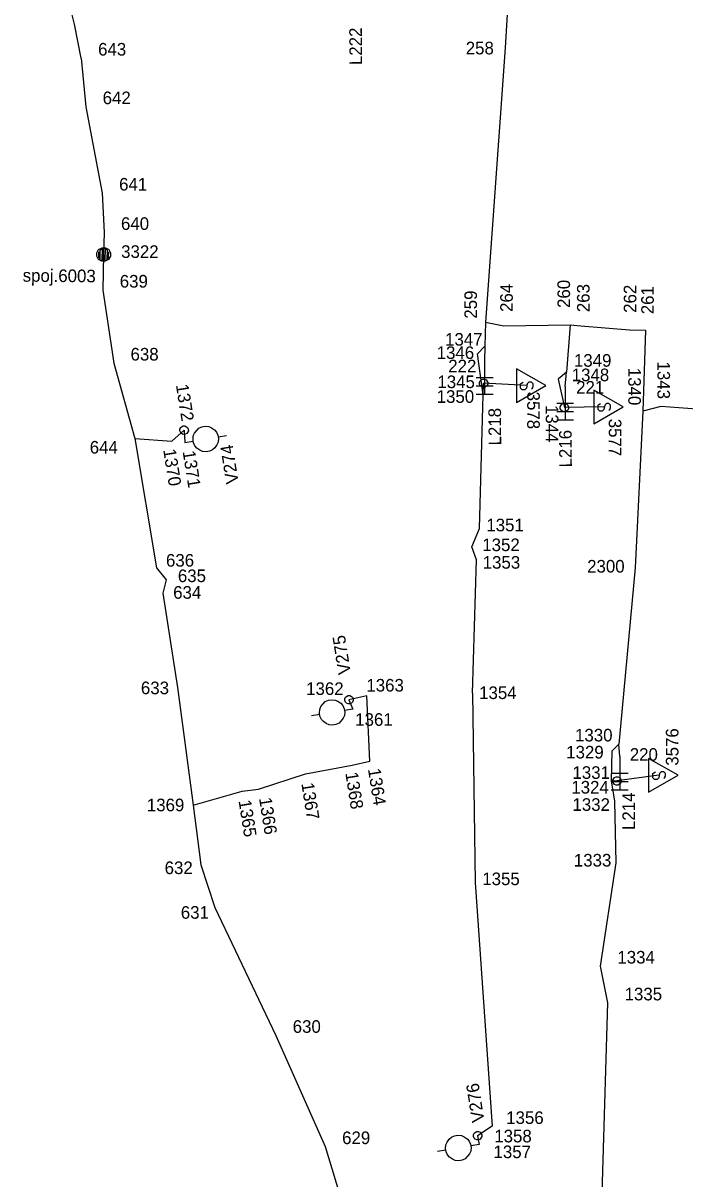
# Model space of a CAD drawing. Extents: x -535557 to -534097, y -1142175 to -1136716.
# Drawn here: x -534529.8 to -534490.4, y -1140672.6 to -1140603.8 of the extents above; entities that cross this region are included whole.
import ezdxf

# ---------------------------------------------------------------- set-up
doc = ezdxf.new("R2010")
doc.units = 0
doc.layers.add('Default', color=7, linetype='Continuous')
doc.layers.add('SS_SZDC', color=7, linetype='Continuous')

# ---------------------------------------------------------------- blocks, each defined once
blk = doc.blocks.new('POINT_DISPLAY')
at = {"layer": 'Default'}
blk.add_line((0, 0), (0, 0), dxfattribs=at)

msp = doc.modelspace()

# ---------------------------------------------------------------- linework, layer by layer
at = {"layer": 'SS_SZDC'}
for p, q in [((-534500.069, -1140588.51), (-534501.09, -1140605.28)), ((-534526.72, -1140603.879), (-534528.6, -1140596)), ((-534526.31, -1140605.889), (-534526.72, -1140603.879)), ((-534501.09, -1140605.28), (-534502.26, -1140621.6)), ((-534526.31, -1140605.889), (-534526.039, -1140608.78)), ((-534526.039, -1140608.78), (-534525.06, -1140613.92)), ((-534525.06, -1140613.92), (-534524.949, -1140616.26)), ((-534524.949, -1140616.26), (-534524.979, -1140617.569)), ((-534525.38, -1140617.666), (-534525.379, -1140617.466)), ((-534525.379, -1140617.466), (-534525.277, -1140617.267)), ((-534525.278, -1140617.417), (-534525.281, -1140617.717)), ((-534525.277, -1140617.267), (-534525.076, -1140617.169)), ((-534525.182, -1140617.868), (-534525.177, -1140617.318)), ((-534525.177, -1140617.318), (-534525.076, -1140617.219)), ((-534525.076, -1140617.219), (-534525.083, -1140617.919)), ((-534525.076, -1140617.169), (-534524.876, -1140617.17)), ((-534524.983, -1140617.919), (-534524.976, -1140617.22)), ((-534524.883, -1140617.92), (-534524.876, -1140617.22)), ((-534524.876, -1140617.17), (-534524.677, -1140617.272)), ((-534524.876, -1140617.22), (-534524.777, -1140617.321)), ((-534524.777, -1140617.321), (-534524.782, -1140617.871)), ((-534524.681, -1140617.722), (-534524.678, -1140617.422)), ((-534524.677, -1140617.272), (-534524.579, -1140617.473)), ((-534524.579, -1140617.473), (-534524.58, -1140617.673)), ((-534525.282, -1140617.867), (-534525.38, -1140617.666)), ((-534525.083, -1140617.969), (-534525.282, -1140617.867)), ((-534525.281, -1140617.717), (-534525.182, -1140617.868)), ((-534525.083, -1140617.919), (-534524.883, -1140617.92)), ((-534524.883, -1140617.97), (-534525.083, -1140617.969)), ((-534524.979, -1140617.569), (-534525.02, -1140619.69)), ((-534524.682, -1140617.872), (-534524.883, -1140617.97)), ((-534524.782, -1140617.871), (-534524.681, -1140617.722)), ((-534524.58, -1140617.673), (-534524.682, -1140617.872)), ((-534525.02, -1140619.69), (-534524.38, -1140624.03)), ((-534502.26, -1140621.6), (-534502.289, -1140623.03)), ((-534502.26, -1140621.6), (-534501.159, -1140621.819)), ((-534501.159, -1140621.819), (-534497.21, -1140621.75)), ((-534497.21, -1140621.75), (-534497.43, -1140624.569)), ((-534497.21, -1140621.75), (-534496.579, -1140621.819)), ((-534496.579, -1140621.819), (-534493.68, -1140622.049)), ((-534493.68, -1140622.049), (-534492.729, -1140622.069)), ((-534492.729, -1140622.069), (-534492.89, -1140626.889)), ((-534502.729, -1140623.489), (-534502.289, -1140623.03)), ((-534502.289, -1140623.03), (-534502.31, -1140623.909)), ((-534502.399, -1140625.92), (-534502.729, -1140623.489)), ((-534524.38, -1140624.03), (-534523.119, -1140628.52)), ((-534502.31, -1140623.909), (-534502.31, -1140625.909)), ((-534500.419, -1140624.37), (-534500.419, -1140626.37)), ((-534498.669, -1140625.37), (-534500.419, -1140624.37)), ((-534501.81, -1140624.909), (-534502.81, -1140624.909)), ((-534502.62, -1140625.181), (-534502.57, -1140625.081)), ((-534502.57, -1140625.081), (-534502.521, -1140625.03)), ((-534502.521, -1140625.03), (-534502.421, -1140624.98)), ((-534502.421, -1140624.98), (-534502.321, -1140624.979)), ((-534502.321, -1140624.979), (-534502.221, -1140625.029)), ((-534502.221, -1140625.029), (-534502.17, -1140625.078)), ((-534502.17, -1140625.078), (-534502.12, -1140625.178)), ((-534497.43, -1140624.569), (-534497.93, -1140624.989)), ((-534497.93, -1140624.989), (-534497.56, -1140626.68)), ((-534497.52, -1140625.43), (-534497.43, -1140624.569)), ((-534501.81, -1140625.409), (-534502.81, -1140625.409)), ((-534502.619, -1140625.281), (-534502.62, -1140625.181)), ((-534502.569, -1140625.381), (-534502.619, -1140625.281)), ((-534502.518, -1140625.43), (-534502.569, -1140625.381)), ((-534502.418, -1140625.48), (-534502.518, -1140625.43)), ((-534502.318, -1140625.479), (-534502.418, -1140625.48)), ((-534502.399, -1140625.92), (-534502.369, -1140625.229)), ((-534499.819, -1140625.37), (-534502.369, -1140625.229)), ((-534502.218, -1140625.429), (-534502.318, -1140625.479)), ((-534502.169, -1140625.378), (-534502.218, -1140625.429)), ((-534502.119, -1140625.278), (-534502.169, -1140625.378)), ((-534502.12, -1140625.178), (-534502.119, -1140625.278)), ((-534500.419, -1140626.37), (-534498.669, -1140625.37)), ((-534500.169, -1140625.27), (-534500.119, -1140625.22)), ((-534500.169, -1140625.52), (-534500.169, -1140625.27)), ((-534500.069, -1140625.62), (-534500.169, -1140625.52)), ((-534500.119, -1140625.22), (-534500.019, -1140625.17)), ((-534499.919, -1140625.62), (-534500.069, -1140625.62)), ((-534499.819, -1140625.52), (-534499.919, -1140625.62)), ((-534499.769, -1140625.27), (-534499.819, -1140625.52)), ((-534499.669, -1140625.17), (-534499.769, -1140625.27)), ((-534499.519, -1140625.17), (-534499.669, -1140625.17)), ((-534499.419, -1140625.27), (-534499.519, -1140625.17)), ((-534499.519, -1140625.57), (-534499.469, -1140625.52)), ((-534499.469, -1140625.52), (-534499.419, -1140625.42)), ((-534499.419, -1140625.42), (-534499.419, -1140625.27)), ((-534497.52, -1140625.43), (-534497.52, -1140627.43)), ((-534495.81, -1140625.639), (-534495.81, -1140627.639)), ((-534494.06, -1140626.639), (-534495.81, -1140625.639)), ((-534501.81, -1140625.909), (-534502.81, -1140625.909)), ((-534502.609, -1140633.879), (-534502.399, -1140625.92)), ((-534497.02, -1140626.43), (-534498.02, -1140626.43)), ((-534497.76, -1140626.531), (-534497.711, -1140626.48)), ((-534497.711, -1140626.48), (-534497.611, -1140626.43)), ((-534497.611, -1140626.43), (-534497.511, -1140626.429)), ((-534497.511, -1140626.429), (-534497.411, -1140626.479)), ((-534497.411, -1140626.479), (-534497.36, -1140626.528)), ((-534495.51, -1140626.489), (-534495.41, -1140626.439)), ((-534495.06, -1140626.439), (-534495.16, -1140626.539)), ((-534494.91, -1140626.439), (-534495.06, -1140626.439)), ((-534494.81, -1140626.539), (-534494.91, -1140626.439)), ((-534497.02, -1140626.93), (-534498.02, -1140626.93)), ((-534497.81, -1140626.631), (-534497.76, -1140626.531)), ((-534497.809, -1140626.731), (-534497.81, -1140626.631)), ((-534497.759, -1140626.831), (-534497.809, -1140626.731)), ((-534497.708, -1140626.88), (-534497.759, -1140626.831)), ((-534497.608, -1140626.93), (-534497.708, -1140626.88)), ((-534497.508, -1140626.929), (-534497.608, -1140626.93)), ((-534495.21, -1140626.639), (-534497.56, -1140626.68)), ((-534497.408, -1140626.879), (-534497.508, -1140626.929)), ((-534497.359, -1140626.828), (-534497.408, -1140626.879)), ((-534497.36, -1140626.528), (-534497.31, -1140626.628)), ((-534497.309, -1140626.728), (-534497.359, -1140626.828)), ((-534497.31, -1140626.628), (-534497.309, -1140626.728)), ((-534495.81, -1140627.639), (-534494.06, -1140626.639)), ((-534495.56, -1140626.539), (-534495.51, -1140626.489)), ((-534495.56, -1140626.789), (-534495.56, -1140626.539)), ((-534495.46, -1140626.889), (-534495.56, -1140626.789)), ((-534495.31, -1140626.889), (-534495.46, -1140626.889)), ((-534495.21, -1140626.789), (-534495.31, -1140626.889)), ((-534495.16, -1140626.539), (-534495.21, -1140626.789)), ((-534494.91, -1140626.839), (-534494.86, -1140626.789)), ((-534494.86, -1140626.789), (-534494.81, -1140626.689)), ((-534494.81, -1140626.689), (-534494.81, -1140626.539)), ((-534492.89, -1140626.889), (-534493.359, -1140636.209)), ((-534491.829, -1140626.61), (-534492.89, -1140626.889)), ((-534489.149, -1140626.809), (-534491.829, -1140626.61)), ((-534520.39, -1140627.871), (-534520.341, -1140627.82)), ((-534520.341, -1140627.82), (-534520.241, -1140627.77)), ((-534520.241, -1140627.77), (-534520.141, -1140627.769)), ((-534520.141, -1140627.769), (-534520.041, -1140627.819)), ((-534520.041, -1140627.819), (-534519.99, -1140627.868)), ((-534519.316, -1140627.904), (-534519.127, -1140627.822)), ((-534519.127, -1140627.822), (-534518.93, -1140627.79)), ((-534518.93, -1140627.79), (-534518.724, -1140627.806)), ((-534518.724, -1140627.806), (-534518.56, -1140627.881)), ((-534497.02, -1140627.43), (-534498.02, -1140627.43)), ((-534523.119, -1140628.52), (-534520.92, -1140628.67)), ((-534523.119, -1140628.52), (-534521.84, -1140636.219)), ((-534520.92, -1140628.67), (-534520.189, -1140628.02)), ((-534520.44, -1140627.971), (-534520.39, -1140627.871)), ((-534520.439, -1140628.071), (-534520.44, -1140627.971)), ((-534520.389, -1140628.171), (-534520.439, -1140628.071)), ((-534520.338, -1140628.22), (-534520.389, -1140628.171)), ((-534520.238, -1140628.27), (-534520.338, -1140628.22)), ((-534520.138, -1140628.269), (-534520.238, -1140628.27)), ((-534520.189, -1140628.02), (-534520.14, -1140628.75)), ((-534520.038, -1140628.219), (-534520.138, -1140628.269)), ((-534519.989, -1140628.168), (-534520.038, -1140628.219)), ((-534519.99, -1140627.868), (-534519.94, -1140627.968)), ((-534519.939, -1140628.068), (-534519.989, -1140628.168)), ((-534519.94, -1140627.968), (-534519.939, -1140628.068)), ((-534519.662, -1140628.569), (-534519.646, -1140628.364)), ((-534519.646, -1140628.364), (-534519.571, -1140628.2)), ((-534519.571, -1140628.2), (-534519.316, -1140627.904)), ((-534518.56, -1140627.881), (-534518.388, -1140628.004)), ((-534518.388, -1140628.004), (-534518.264, -1140628.136)), ((-534518.264, -1140628.136), (-534518.183, -1140628.325)), ((-534518.183, -1140628.325), (-534518.15, -1140628.522)), ((-534518.15, -1140628.522), (-534518.167, -1140628.728)), ((-534518.166, -1140628.424), (-534517.673, -1140628.342)), ((-534520.14, -1140628.75), (-534519.646, -1140628.668)), ((-534519.646, -1140628.668), (-534519.662, -1140628.569)), ((-534519.63, -1140628.767), (-534519.646, -1140628.668)), ((-534519.548, -1140628.956), (-534519.63, -1140628.767)), ((-534519.425, -1140629.088), (-534519.548, -1140628.956)), ((-534519.252, -1140629.211), (-534519.425, -1140629.088)), ((-534519.088, -1140629.285), (-534519.252, -1140629.211)), ((-534518.496, -1140629.188), (-534518.685, -1140629.27)), ((-534518.364, -1140629.065), (-534518.496, -1140629.188)), ((-534518.241, -1140628.892), (-534518.364, -1140629.065)), ((-534518.167, -1140628.728), (-534518.241, -1140628.892)), ((-534518.883, -1140629.302), (-534519.088, -1140629.285)), ((-534518.685, -1140629.27), (-534518.883, -1140629.302)), ((-534503.069, -1140634.959), (-534502.609, -1140633.879)), ((-534502.789, -1140635.739), (-534503.069, -1140634.959)), ((-534503.029, -1140643.67), (-534502.789, -1140635.739)), ((-534521.84, -1140636.219), (-534521.25, -1140636.92)), ((-534493.359, -1140636.209), (-534494.319, -1140646.709)), ((-534521.25, -1140636.92), (-534521.46, -1140637.709)), ((-534521.46, -1140637.709), (-534520.59, -1140643.329)), ((-534520.59, -1140643.329), (-534519.649, -1140650.329)), ((-534512.048, -1140644.467), (-534511.925, -1140644.294)), ((-534511.925, -1140644.294), (-534511.793, -1140644.171)), ((-534511.793, -1140644.171), (-534511.604, -1140644.089)), ((-534511.604, -1140644.089), (-534511.406, -1140644.057)), ((-534511.406, -1140644.057), (-534511.201, -1140644.074)), ((-534511.201, -1140644.074), (-534511.037, -1140644.148)), ((-534511.037, -1140644.148), (-534510.864, -1140644.271)), ((-534510.864, -1140644.271), (-534510.741, -1140644.403)), ((-534510.63, -1140644.011), (-534510.58, -1140643.911)), ((-534510.629, -1140644.111), (-534510.63, -1140644.011)), ((-534510.579, -1140644.211), (-534510.629, -1140644.111)), ((-534510.58, -1140643.911), (-534510.531, -1140643.86)), ((-534510.528, -1140644.26), (-534510.579, -1140644.211)), ((-534510.531, -1140643.86), (-534510.431, -1140643.81)), ((-534510.428, -1140644.31), (-534510.528, -1140644.26)), ((-534510.431, -1140643.81), (-534510.331, -1140643.809)), ((-534510.328, -1140644.309), (-534510.428, -1140644.31)), ((-534509.319, -1140643.819), (-534510.38, -1140644.059)), ((-534510.38, -1140644.059), (-534510.149, -1140644.61)), ((-534510.331, -1140643.809), (-534510.231, -1140643.859)), ((-534510.228, -1140644.259), (-534510.328, -1140644.309)), ((-534510.231, -1140643.859), (-534510.18, -1140643.908)), ((-534510.179, -1140644.208), (-534510.228, -1140644.259)), ((-534510.18, -1140643.908), (-534510.13, -1140644.008)), ((-534510.129, -1140644.108), (-534510.179, -1140644.208)), ((-534510.13, -1140644.008), (-534510.129, -1140644.108)), ((-534509.14, -1140647.719), (-534509.319, -1140643.819)), ((-534503.029, -1140643.67), (-534502.88, -1140654.93)), ((-534512.123, -1140644.935), (-534512.616, -1140645.017)), ((-534512.139, -1140644.837), (-534512.122, -1140644.631)), ((-534512.106, -1140645.034), (-534512.139, -1140644.837)), ((-534512.122, -1140644.631), (-534512.048, -1140644.467)), ((-534512.025, -1140645.223), (-534512.106, -1140645.034)), ((-534510.741, -1140644.403), (-534510.659, -1140644.592)), ((-534510.643, -1140644.995), (-534510.718, -1140645.159)), ((-534510.659, -1140644.592), (-534510.643, -1140644.691)), ((-534510.149, -1140644.61), (-534510.643, -1140644.691)), ((-534510.643, -1140644.691), (-534510.627, -1140644.79)), ((-534510.627, -1140644.79), (-534510.643, -1140644.995)), ((-534511.901, -1140645.355), (-534512.025, -1140645.223)), ((-534511.729, -1140645.478), (-534511.901, -1140645.355)), ((-534511.565, -1140645.553), (-534511.729, -1140645.478)), ((-534511.359, -1140645.569), (-534511.565, -1140645.553)), ((-534511.162, -1140645.537), (-534511.359, -1140645.569)), ((-534510.973, -1140645.455), (-534511.162, -1140645.537)), ((-534510.718, -1140645.159), (-534510.973, -1140645.455)), ((-534494.76, -1140648.879), (-534494.72, -1140647.1)), ((-534494.72, -1140647.1), (-534494.319, -1140646.709)), ((-534494.27, -1140647.44), (-534494.319, -1140646.709)), ((-534510.189, -1140647.94), (-534509.14, -1140647.719)), ((-534494.27, -1140647.44), (-534494.27, -1140649.44)), ((-534492.549, -1140647.549), (-534492.549, -1140649.549)), ((-534490.799, -1140648.549), (-534492.549, -1140647.549)), ((-534515.76, -1140649.379), (-534512.97, -1140648.459)), ((-534512.97, -1140648.459), (-534510.189, -1140647.94)), ((-534493.77, -1140648.44), (-534494.77, -1140648.44)), ((-534492.299, -1140648.449), (-534492.249, -1140648.399)), ((-534492.299, -1140648.699), (-534492.299, -1140648.449)), ((-534492.249, -1140648.399), (-534492.149, -1140648.349)), ((-534491.899, -1140648.449), (-534491.949, -1140648.699)), ((-534491.799, -1140648.349), (-534491.899, -1140648.449)), ((-534491.649, -1140648.349), (-534491.799, -1140648.349)), ((-534491.549, -1140648.449), (-534491.649, -1140648.349)), ((-534491.549, -1140648.599), (-534491.549, -1140648.449)), ((-534493.77, -1140648.94), (-534494.77, -1140648.94)), ((-534494.56, -1140650.1), (-534494.76, -1140648.879)), ((-534494.76, -1140648.879), (-534494.43, -1140648.889)), ((-534494.68, -1140648.841), (-534494.63, -1140648.741)), ((-534494.679, -1140648.941), (-534494.68, -1140648.841)), ((-534494.629, -1140649.041), (-534494.679, -1140648.941)), ((-534494.63, -1140648.741), (-534494.581, -1140648.69)), ((-534494.578, -1140649.09), (-534494.629, -1140649.041)), ((-534494.581, -1140648.69), (-534494.481, -1140648.64)), ((-534494.478, -1140649.14), (-534494.578, -1140649.09)), ((-534494.481, -1140648.64), (-534494.381, -1140648.639)), ((-534494.378, -1140649.139), (-534494.478, -1140649.14)), ((-534491.949, -1140648.549), (-534494.43, -1140648.889)), ((-534494.381, -1140648.639), (-534494.281, -1140648.689)), ((-534494.278, -1140649.089), (-534494.378, -1140649.139)), ((-534494.281, -1140648.689), (-534494.23, -1140648.738)), ((-534494.229, -1140649.038), (-534494.278, -1140649.089)), ((-534494.23, -1140648.738), (-534494.18, -1140648.838)), ((-534494.179, -1140648.938), (-534494.229, -1140649.038)), ((-534494.18, -1140648.838), (-534494.179, -1140648.938)), ((-534492.549, -1140649.549), (-534490.799, -1140648.549)), ((-534492.199, -1140648.799), (-534492.299, -1140648.699)), ((-534492.049, -1140648.799), (-534492.199, -1140648.799)), ((-534491.949, -1140648.699), (-534492.049, -1140648.799)), ((-534491.649, -1140648.749), (-534491.599, -1140648.699)), ((-534491.599, -1140648.699), (-534491.549, -1140648.599)), ((-534519.649, -1140650.329), (-534516.729, -1140649.5)), ((-534516.729, -1140649.5), (-534515.76, -1140649.379)), ((-534493.77, -1140649.44), (-534494.77, -1140649.44)), ((-534519.649, -1140650.329), (-534519.199, -1140653.879)), ((-534494.479, -1140653.76), (-534494.56, -1140650.1)), ((-534519.199, -1140653.879), (-534518.369, -1140656.42)), ((-534495.409, -1140659.899), (-534494.479, -1140653.76)), ((-534502.88, -1140654.93), (-534501.869, -1140669.43)), ((-534518.369, -1140656.42), (-534514.729, -1140664.02)), ((-534494.979, -1140662.09), (-534495.409, -1140659.899)), ((-534495.34, -1140674.549), (-534494.979, -1140662.09)), ((-534514.729, -1140664.02), (-534511.789, -1140670.639)), ((-534502.93, -1140669.841), (-534502.881, -1140669.79)), ((-534502.881, -1140669.79), (-534502.781, -1140669.74)), ((-534502.781, -1140669.74), (-534502.681, -1140669.739)), ((-534501.869, -1140669.43), (-534502.729, -1140669.989)), ((-534502.681, -1140669.739), (-534502.581, -1140669.789)), ((-534502.581, -1140669.789), (-534502.53, -1140669.838)), ((-534504.612, -1140670.541), (-534504.538, -1140670.377)), ((-534504.538, -1140670.377), (-534504.415, -1140670.204)), ((-534504.415, -1140670.204), (-534504.283, -1140670.081)), ((-534504.283, -1140670.081), (-534504.094, -1140669.999)), ((-534504.094, -1140669.999), (-534503.896, -1140669.967)), ((-534503.896, -1140669.967), (-534503.691, -1140669.984)), ((-534503.691, -1140669.984), (-534503.527, -1140670.058)), ((-534503.527, -1140670.058), (-534503.354, -1140670.181)), ((-534503.354, -1140670.181), (-534503.231, -1140670.313)), ((-534503.231, -1140670.313), (-534503.149, -1140670.502)), ((-534502.98, -1140669.941), (-534502.93, -1140669.841)), ((-534502.979, -1140670.041), (-534502.98, -1140669.941)), ((-534502.929, -1140670.141), (-534502.979, -1140670.041)), ((-534502.878, -1140670.19), (-534502.929, -1140670.141)), ((-534502.778, -1140670.24), (-534502.878, -1140670.19)), ((-534502.678, -1140670.239), (-534502.778, -1140670.24)), ((-534502.729, -1140669.989), (-534502.64, -1140670.52)), ((-534502.578, -1140670.189), (-534502.678, -1140670.239)), ((-534502.529, -1140670.138), (-534502.578, -1140670.189)), ((-534502.53, -1140669.838), (-534502.48, -1140669.938)), ((-534502.479, -1140670.038), (-534502.529, -1140670.138)), ((-534502.48, -1140669.938), (-534502.479, -1140670.038)), ((-534511.789, -1140670.639), (-534508.64, -1140681.1)), ((-534504.613, -1140670.845), (-534505.106, -1140670.927)), ((-534504.629, -1140670.747), (-534504.612, -1140670.541)), ((-534504.596, -1140670.944), (-534504.629, -1140670.747)), ((-534504.515, -1140671.133), (-534504.596, -1140670.944)), ((-534504.391, -1140671.265), (-534504.515, -1140671.133)), ((-534503.208, -1140671.069), (-534503.463, -1140671.365)), ((-534503.133, -1140670.905), (-534503.208, -1140671.069)), ((-534503.149, -1140670.502), (-534503.133, -1140670.601)), ((-534502.64, -1140670.52), (-534503.133, -1140670.601)), ((-534503.133, -1140670.601), (-534503.117, -1140670.7)), ((-534503.117, -1140670.7), (-534503.133, -1140670.905)), ((-534504.219, -1140671.388), (-534504.391, -1140671.265)), ((-534504.055, -1140671.463), (-534504.219, -1140671.388)), ((-534503.849, -1140671.479), (-534504.055, -1140671.463)), ((-534503.652, -1140671.447), (-534503.849, -1140671.479)), ((-534503.463, -1140671.365), (-534503.652, -1140671.447))]:
    msp.add_line(p, q, dxfattribs=at)

# ---------------------------------------------------------------- block references
for p in [(-534526.72, -1140603.879), (-534501.09, -1140605.28), (-534526.31, -1140605.889), (-534526.039, -1140608.78), (-534525.06, -1140613.92), (-534524.949, -1140616.26), (-534524.979, -1140617.569), (-534525.02, -1140619.69), (-534502.26, -1140621.6), (-534501.159, -1140621.819), (-534497.21, -1140621.75), (-534496.579, -1140621.819), (-534493.68, -1140622.049), (-534492.729, -1140622.069), (-534502.289, -1140623.03), (-534502.729, -1140623.489), (-534524.38, -1140624.03), (-534502.31, -1140623.909), (-534497.93, -1140624.989), (-534497.43, -1140624.569), (-534502.369, -1140625.229), (-534502.369, -1140625.229), (-534499.819, -1140625.37), (-534497.52, -1140625.43), (-534502.399, -1140625.92), (-534497.56, -1140626.68), (-534497.56, -1140626.68), (-534495.21, -1140626.639), (-534492.89, -1140626.889), (-534491.829, -1140626.61), (-534523.119, -1140628.52), (-534520.189, -1140628.02), (-534520.189, -1140628.02), (-534520.92, -1140628.67), (-534520.14, -1140628.75), (-534502.609, -1140633.879), (-534503.069, -1140634.959), (-534502.789, -1140635.739), (-534521.84, -1140636.219), (-534493.359, -1140636.209), (-534521.25, -1140636.92), (-534521.46, -1140637.709), (-534520.59, -1140643.329), (-534510.38, -1140644.059), (-534510.38, -1140644.059), (-534509.319, -1140643.819), (-534503.029, -1140643.67), (-534510.149, -1140644.61), (-534494.72, -1140647.1), (-534494.319, -1140646.709), (-534509.14, -1140647.719), (-534494.27, -1140647.44), (-534512.97, -1140648.459), (-534510.189, -1140647.94), (-534494.76, -1140648.879), (-534494.43, -1140648.889), (-534494.43, -1140648.889), (-534491.949, -1140648.549), (-534516.729, -1140649.5), (-534515.76, -1140649.379), (-534519.649, -1140650.329), (-534494.56, -1140650.1), (-534519.199, -1140653.879), (-534494.479, -1140653.76), (-534502.88, -1140654.93), (-534518.369, -1140656.42), (-534495.409, -1140659.899), (-534494.979, -1140662.09), (-534514.729, -1140664.02), (-534501.869, -1140669.43), (-534502.729, -1140669.989), (-534502.729, -1140669.989), (-534511.789, -1140670.639), (-534502.64, -1140670.52)]:
    msp.add_blockref('POINT_DISPLAY', p, dxfattribs=at)

# ---------------------------------------------------------------- texts
for s, rotation, p in [('L222', 90.37563, (-534509.601, -1140606.304)), ('spoj.6003', 359.47566, (-534529.801, -1140619.189)), ('264', 90, (-534500.632, -1140620.99)), ('260', 90, (-534497.226, -1140620.753)), ('263', 90, (-534496.063, -1140621.003)), ('262', 90, (-534493.28, -1140621.044)), ('261', 90, (-534492.241, -1140621.127)), ('259', 90, (-534502.764, -1140621.39)), ('1340', 270, (-534493.76, -1140624.314)), ('1343', 270, (-534492.026, -1140623.938)), ('1372', 279, (-534520.684, -1140625.335)), ('3578', 270, (-534499.776, -1140625.729)), ('L218', 90.37563, (-534501.321, -1140628.93)), ('1344', 270, (-534498.669, -1140626.522)), ('3577', 270, (-534494.92, -1140627.341)), ('L216', 90.37563, (-534497.118, -1140630.238)), ('1370', 279, (-534521.438, -1140629.19)), ('V274', 99, (-534516.94, -1140631.155)), ('1371', 279, (-534520.282, -1140629.291)), ('V275', 99, (-534510.262, -1140642.488)), ('3576', 90, (-534490.774, -1140647.984)), ('1368', 279, (-534510.602, -1140648.413)), ('1364', 279, (-534509.255, -1140648.188)), ('1367', 279, (-534513.217, -1140649.038)), ('L214', 90.37563, (-534493.354, -1140651.805)), ('1365', 279, (-534516.955, -1140650.065)), ('1366', 279, (-534515.736, -1140649.921)), ('V276', 99, (-534502.31, -1140669.132))]:
    msp.add_text(s, height=0.75, rotation=rotation, dxfattribs=at).set_placement(p)
for s, p in [('643', (-534525.31, -1140605.739)), ('258', (-534503.433, -1140605.669)), ('642', (-534525.039, -1140608.63)), ('641', (-534524.06, -1140613.77)), ('640', (-534523.949, -1140616.11)), ('3322', (-534523.938, -1140617.776)), ('639', (-534524.02, -1140619.54)), ('1347', (-534504.661, -1140622.994)), ('1346', (-534505.162, -1140623.787)), ('638', (-534523.38, -1140623.88)), ('1349', (-534496.994, -1140624.249)), ('222', (-534504.473, -1140624.58)), ('1348', (-534497.126, -1140625.108)), ('1345', (-534505.12, -1140625.52)), ('221', (-534496.862, -1140625.848)), ('1350', (-534505.162, -1140626.397)), ('644', (-534525.807, -1140629.414)), ('1351', (-534502.208, -1140634.037)), ('1352', (-534502.449, -1140635.217)), ('636', (-534521.27, -1140636.139)), ('1353', (-534502.423, -1140636.262)), ('2300', (-534496.209, -1140636.492)), ('635', (-534520.562, -1140637.06)), ('634', (-534520.842, -1140638.049)), ('633', (-534522.763, -1140643.728)), ('1363', (-534509.345, -1140643.57)), ('1362', (-534512.93, -1140643.772)), ('1354', (-534502.637, -1140644.016)), ('1361', (-534510.01, -1140645.608)), ('1330', (-534496.928, -1140646.538)), ('1329', (-534497.455, -1140647.551)), ('220', (-534493.673, -1140647.688)), ('1331', (-534497.082, -1140648.764)), ('1324', (-534497.15, -1140649.637)), ('1369', (-534522.41, -1140650.691)), ('1332', (-534497.082, -1140650.667)), ('1333', (-534496.999, -1140653.978)), ('632', (-534521.351, -1140654.429)), ('1355', (-534502.449, -1140655.086)), ('631', (-534520.388, -1140657.084)), ('1334', (-534494.409, -1140659.749)), ('1335', (-534493.979, -1140661.94)), ('630', (-534513.729, -1140663.87)), ('1356', (-534501.026, -1140669.291)), ('629', (-534510.789, -1140670.489)), ('1358', (-534501.734, -1140670.387)), ('1357', (-534501.78, -1140671.324))]:
    msp.add_text(s, height=0.75, dxfattribs=at).set_placement(p)

doc.saveas('drawing.dxf')
